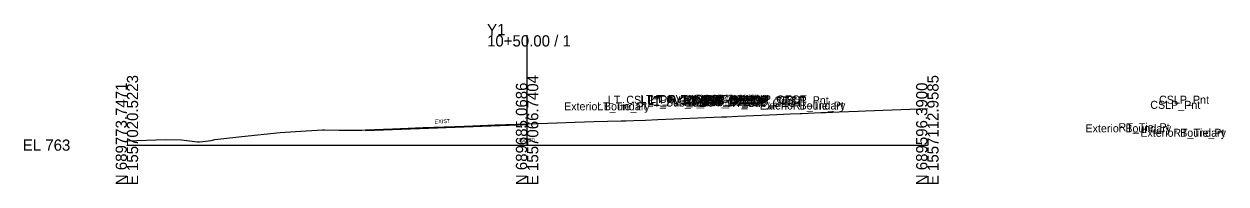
# Model space of a CAD drawing. Extents: x -26 to 303, y -10 to 5005.
# Drawn here: x -25.7 to 274.6, y 490.3 to 530.2 of the extents above; entities that cross this region are included whole.
import ezdxf

# ---------------------------------------------------------------- set-up
doc = ezdxf.new("R2010")
doc.units = 0
for name, color, linetype in [('Default', 7, 'Continuous'), ('Exist Cross Section Cell', 7, 'Continuous'), ('Exist XS Center Line Elevation Label', 7, 'Continuous'), ('Exist XS Ground Line', 7, 'Continuous'), ('Prop CMT Pvmt Course 1', 7, 'Continuous'), ('Prop CMT Pvmt Surface', 7, 'Continuous'), ('Prop XS SE Text', 7, 'Continuous')]:
    doc.layers.add(name, color=color, linetype=linetype)

msp = doc.modelspace()

# ---------------------------------------------------------------- linework, layer by layer
at = {"layer": 'Exist Cross Section Cell'}
for p, q in [((100, 500), (100, 527.41)), ((0, 500), (100, 500)), ((100, 500), (200, 500))]:
    msp.add_line(p, q, dxfattribs=at)
at = {"layer": 'Exist XS Ground Line'}
msp.add_lwpolyline([(0, 501.04), (9.73, 501.43), (13.67, 501.32), (17.64, 500.84), (18.16, 500.8), (19, 500.9), (21.05, 501.15), (21.99, 501.38), (28.76, 502.16), (38.3, 503.12), (42.16, 503.4), (48.84, 503.78), (49.41, 503.79), (53.06, 503.69), (58.7, 503.74), (59.94, 503.8), (62.73, 503.9), (74.01, 504.41), (84.55, 504.76), (92.06, 505.02), (100, 505.3), (102.8, 505.39), (116.68, 505.89), (123.54, 506.04), (124.7, 506.06), (126.61, 506.14), (129.56, 506.25), (132.66, 506.37), (148.69, 507.05), (149.87, 507.09), (152.61, 507.21), (162.42, 507.64), (165.76, 507.78), (168.21, 507.87), (168.63, 507.89), (173.41, 508.1), (174.63, 508.16), (177.97, 508.3), (182.72, 508.49), (184.53, 508.56), (200, 509.14)], dxfattribs=at)
at = {"layer": 'Prop CMT Pvmt Course 1'}
for p, q in [((59.6, 503.66), (100, 505.17)), ((59.6, 503.78), (59.6, 503.66))]:
    msp.add_line(p, q, dxfattribs=at)
for points in [[(100, 505.3), (100, 505.17)], [(100, 505.17), (100, 505.3)]]:
    msp.add_lwpolyline(points, dxfattribs=at)
at = {"layer": 'Prop CMT Pvmt Surface'}
msp.add_line((59.6, 503.78), (100, 505.3), dxfattribs=at)

# ---------------------------------------------------------------- texts
at = {"layer": 'Default'}
for s, height, p in [('Exterior Boundary', 2, (109.23, 508.67)), ('LT_Tie_Pt', 2, (117.53, 508.67)), ('LT_CSLP_Pnt', 2, (120.17, 510.3)), ('LT_CG_Top_BOC', 2, (128.28, 510.5)), ('LT_Sub_OEOT', 2, (130.08, 509.63)), ('LT_PV2_OEOT', 2, (130.17, 510.25)), ('LT_PV3_OEOT', 2, (130.17, 510)), ('LT_PV1_OEOT', 2, (130.74, 510.5)), ('RT_Sub_OEEOP', 2, (139.17, 509.73)), ('LT_Sub_OEEOP', 2, (139.21, 509.73)), ('RT_PV2_OEEOP', 2, (139.26, 510.35)), ('RT_PV3_OEEOP', 2, (139.26, 510.1)), ('LT_PV2_OEEOP', 2, (139.31, 510.35)), ('LT_PV3_OEEOP', 2, (139.31, 510.1)), ('RT_PV1_OEEOP', 2, (139.83, 510.48)), ('LT_PV1_OEEOP', 2, (139.87, 510.48)), ('RT_PV2_IEEOP', 2, (139.91, 510.35)), ('LT_PV2_IEEOP', 2, (139.95, 510.35)), ('RT_PV1_IEEOP', 2, (140.47, 510.48)), ('LT_PV1_IEEOP', 2, (140.52, 510.48)), ('RT_PV2_PGL', 2, (141.17, 510.35)), ('LT_PV2_PGL', 2, (141.21, 510.35)), ('RT_PV1_PGL', 2, (141.73, 510.6)), ('LT_PV1_PGL', 2, (141.78, 510.6)), ('RT_Sub_OEOT', 2, (150.03, 509.53)), ('RT_PV2_OEOT', 2, (150.13, 510.15)), ('RT_PV3_OEOT', 2, (150.13, 509.9)), ('RT_PV1_OEOT', 2, (150.69, 510.4)), ('Exterior Boundary', 2, (158.1, 508.88)), ('CSLP_Pnt', 2, (162.87, 510.2)), ('RT_Tie_Pt', 2, (166.35, 508.88)), ('CSLP_Pnt', 2, (255.7, 509.05)), ('CSLP_Pnt', 2, (257.89, 510.33)), ('Exterior Boundary', 2, (239.51, 503.18)), ('RT_Tie_Pt', 2, (247.77, 503.47)), ('Exterior Boundary', 2, (253.21, 502.08)), ('RT_Tie_Pt', 2, (261.46, 502.08)), ('-', 0.0001, (0, 500))]:
    msp.add_text(s, height=height, dxfattribs=at).set_placement(p)
at = {"layer": 'Exist Cross Section Cell'}
for s, p in [('Y1', (90, 527.41)), ('10+50.00 / 1', (90, 524.61)), ('EL 763', (-26, 498.6))]:
    msp.add_text(s, height=2.8, dxfattribs=at).set_placement(p)
for s, p in [('E 1557020.5223', (2.8, 490)), ('E 1557066.7404', (102.8, 490)), ('E 1557112.9585', (202.8, 490)), ('N 689773.7471', (0, 490)), ('N 689685.0686', (100, 490)), ('N 689596.3900', (200, 490))]:
    msp.add_text(s, height=2.8, rotation=90, dxfattribs=at).set_placement(p)
at = {"layer": 'Exist XS Center Line Elevation Label'}
msp.add_text('768.30', height=1, dxfattribs=at).set_placement((97.67, 500.8))
at = {"layer": 'Prop XS SE Text'}
msp.add_text('EXIST', height=1, rotation=2.147, dxfattribs=at).set_placement((76.88, 505.37))

doc.saveas('drawing.dxf')
